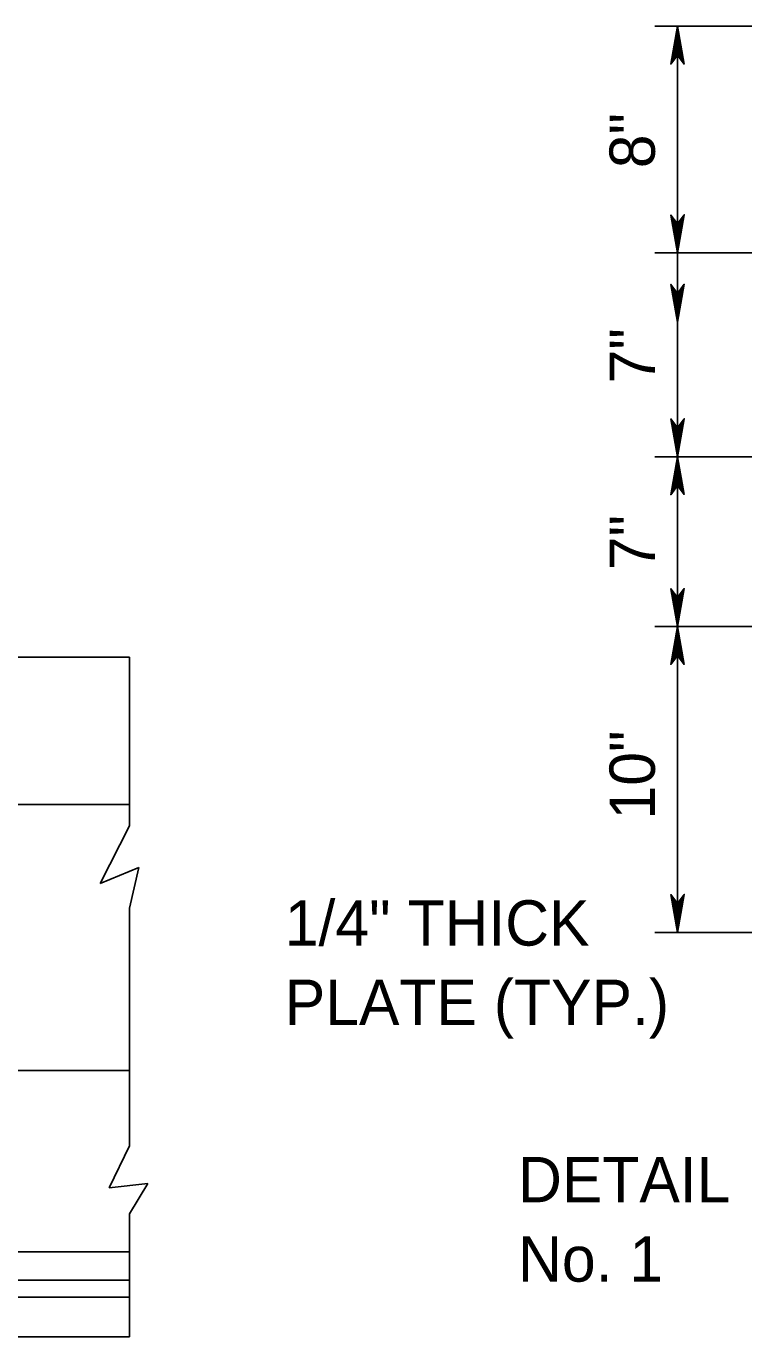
# Model space of a CAD drawing. Extents: x 499866 to 500993, y 499985 to 500645.
# Drawn here: x 500238.9 to 500302.2, y 500462.6 to 500578.2 of the extents above; entities that cross this region are included whole.
import ezdxf

# ---------------------------------------------------------------- set-up
doc = ezdxf.new("R2010")
doc.units = 0
doc.layers.add('24', color=7, linetype='Continuous')
doc.layers.add('5', color=7, linetype='Continuous')

msp = doc.modelspace()

# ---------------------------------------------------------------- linework, layer by layer
at = {"layer": '24'}
for points in [[(500296.34, 500578.18), (500295.74, 500574.83), (500296.34, 500575.63), (500296.92, 500574.84), (500296.34, 500578.18), (500296.34, 500577.95), (500295.79, 500574.92), (500296.34, 500575.69), (500296.87, 500574.98), (500296.35, 500577.83), (500296.34, 500577.72), (500295.87, 500575.12), (500296.34, 500575.71), (500296.8, 500575.11), (500296.34, 500577.67), (500296.35, 500577.56), (500295.94, 500575.29), (500296.34, 500575.73), (500296.74, 500575.28), (500296.35, 500577.24), (500296.35, 500577.05), (500296.03, 500575.46), (500296.33, 500575.77), (500296.66, 500575.43), (500296.34, 500577.01), (500296.33, 500576.83), (500296.12, 500575.64), (500296.35, 500575.87), (500296.58, 500575.62), (500296.34, 500576.67), (500296.32, 500576.5), (500296.18, 500575.78), (500296.34, 500575.9), (500296.52, 500575.71), (500296.34, 500576.41), (500296.22, 500575.95), (500296.35, 500576.01), (500296.48, 500575.81), (500296.35, 500576.3), (500296.28, 500575.99), (500296.38, 500576.12), (500296.44, 500575.97), (500296.34, 500576.12), (500296.33, 500576.04)], [(500296.34, 500558.19), (500296.93, 500561.54), (500296.34, 500560.74), (500295.75, 500561.52), (500296.34, 500558.19), (500296.33, 500558.41), (500296.88, 500561.45), (500296.33, 500560.68), (500295.8, 500561.39), (500296.32, 500558.53), (500296.34, 500558.65), (500296.8, 500561.24), (500296.33, 500560.66), (500295.87, 500561.26), (500296.34, 500558.7), (500296.32, 500558.81), (500296.73, 500561.08), (500296.34, 500560.64), (500295.93, 500561.09), (500296.32, 500559.13), (500296.32, 500559.32), (500296.65, 500560.91), (500296.35, 500560.6), (500296.01, 500560.93), (500296.34, 500559.35), (500296.35, 500559.53), (500296.55, 500560.73), (500296.32, 500560.5), (500296.09, 500560.75), (500296.34, 500559.7), (500296.35, 500559.87), (500296.49, 500560.58), (500296.33, 500560.47), (500296.15, 500560.66), (500296.34, 500559.95), (500296.45, 500560.42), (500296.32, 500560.35), (500296.19, 500560.56), (500296.32, 500560.07), (500296.4, 500560.38), (500296.3, 500560.25), (500296.23, 500560.4), (500296.33, 500560.25), (500296.35, 500560.33)], [(500296.34, 500552.06), (500296.93, 500555.41), (500296.34, 500554.61), (500295.75, 500555.4), (500296.34, 500552.06), (500296.33, 500552.29), (500296.88, 500555.32), (500296.33, 500554.55), (500295.8, 500555.26), (500296.32, 500552.41), (500296.34, 500552.52), (500296.8, 500555.12), (500296.33, 500554.53), (500295.87, 500555.13), (500296.34, 500552.57), (500296.32, 500552.68), (500296.73, 500554.95), (500296.34, 500554.51), (500295.93, 500554.96), (500296.32, 500553), (500296.32, 500553.19), (500296.65, 500554.78), (500296.35, 500554.47), (500296.01, 500554.81), (500296.34, 500553.23), (500296.35, 500553.4), (500296.55, 500554.6), (500296.32, 500554.37), (500296.09, 500554.62), (500296.34, 500553.57), (500296.35, 500553.74), (500296.49, 500554.46), (500296.33, 500554.34), (500296.15, 500554.53), (500296.34, 500553.83), (500296.45, 500554.29), (500296.32, 500554.23), (500296.19, 500554.43), (500296.32, 500553.94), (500296.4, 500554.25), (500296.3, 500554.12), (500296.23, 500554.27), (500296.33, 500554.12), (500296.35, 500554.2)], [(500296.34, 500540.2), (500296.93, 500543.55), (500296.34, 500542.75), (500295.75, 500543.54), (500296.34, 500540.2), (500296.33, 500540.43), (500296.88, 500543.46), (500296.33, 500542.69), (500295.8, 500543.4), (500296.32, 500540.55), (500296.34, 500540.66), (500296.8, 500543.26), (500296.33, 500542.67), (500295.87, 500543.27), (500296.34, 500540.71), (500296.32, 500540.82), (500296.73, 500543.09), (500296.34, 500542.65), (500295.93, 500543.1), (500296.32, 500541.14), (500296.32, 500541.33), (500296.65, 500542.92), (500296.35, 500542.61), (500296.01, 500542.95), (500296.34, 500541.37), (500296.35, 500541.55), (500296.55, 500542.74), (500296.32, 500542.51), (500296.09, 500542.76), (500296.34, 500541.71), (500296.35, 500541.88), (500296.49, 500542.6), (500296.33, 500542.48), (500296.15, 500542.67), (500296.34, 500541.97), (500296.45, 500542.44), (500296.32, 500542.37), (500296.19, 500542.57), (500296.32, 500542.08), (500296.4, 500542.39), (500296.3, 500542.26), (500296.23, 500542.41), (500296.33, 500542.26), (500296.35, 500542.34)], [(500296.34, 500540.2), (500295.74, 500536.85), (500296.34, 500537.66), (500296.92, 500536.87), (500296.34, 500540.2), (500296.34, 500539.98), (500295.79, 500536.95), (500296.34, 500537.72), (500296.87, 500537.01), (500296.35, 500539.86), (500296.34, 500539.75), (500295.87, 500537.15), (500296.34, 500537.73), (500296.8, 500537.14), (500296.34, 500539.7), (500296.35, 500539.59), (500295.94, 500537.32), (500296.34, 500537.76), (500296.74, 500537.31), (500296.35, 500539.26), (500296.35, 500539.08), (500296.03, 500537.49), (500296.33, 500537.79), (500296.66, 500537.46), (500296.34, 500539.04), (500296.33, 500538.86), (500296.12, 500537.67), (500296.35, 500537.9), (500296.58, 500537.65), (500296.34, 500538.7), (500296.32, 500538.53), (500296.18, 500537.81), (500296.34, 500537.93), (500296.52, 500537.73), (500296.34, 500538.44), (500296.22, 500537.97), (500296.35, 500538.04), (500296.48, 500537.84), (500296.35, 500538.32), (500296.28, 500538.02), (500296.38, 500538.15), (500296.44, 500538), (500296.34, 500538.15), (500296.33, 500538.07)], [(500296.34, 500525.22), (500296.93, 500528.57), (500296.34, 500527.77), (500295.75, 500528.55), (500296.34, 500525.22), (500296.33, 500525.44), (500296.88, 500528.47), (500296.33, 500527.7), (500295.8, 500528.41), (500296.32, 500525.56), (500296.34, 500525.67), (500296.8, 500528.27), (500296.33, 500527.69), (500295.87, 500528.29), (500296.34, 500525.72), (500296.32, 500525.83), (500296.73, 500528.1), (500296.34, 500527.66), (500295.93, 500528.11), (500296.32, 500526.16), (500296.32, 500526.35), (500296.65, 500527.94), (500296.35, 500527.63), (500296.01, 500527.96), (500296.34, 500526.38), (500296.35, 500526.56), (500296.55, 500527.75), (500296.32, 500527.52), (500296.09, 500527.77), (500296.34, 500526.72), (500296.35, 500526.89), (500296.49, 500527.61), (500296.33, 500527.49), (500296.15, 500527.69), (500296.34, 500526.98), (500296.45, 500527.45), (500296.32, 500527.38), (500296.19, 500527.58), (500296.32, 500527.1), (500296.4, 500527.4), (500296.3, 500527.27), (500296.23, 500527.42), (500296.33, 500527.28), (500296.35, 500527.35)], [(500296.34, 500525.22), (500295.74, 500521.87), (500296.34, 500522.67), (500296.92, 500521.88), (500296.34, 500525.22), (500296.34, 500524.99), (500295.79, 500521.96), (500296.34, 500522.73), (500296.87, 500522.02), (500296.35, 500524.87), (500296.34, 500524.76), (500295.87, 500522.16), (500296.34, 500522.75), (500296.8, 500522.15), (500296.34, 500524.71), (500296.35, 500524.6), (500295.94, 500522.33), (500296.34, 500522.77), (500296.74, 500522.32), (500296.35, 500524.28), (500296.35, 500524.09), (500296.03, 500522.5), (500296.33, 500522.81), (500296.66, 500522.47), (500296.34, 500524.05), (500296.33, 500523.87), (500296.12, 500522.68), (500296.35, 500522.91), (500296.58, 500522.66), (500296.34, 500523.71), (500296.32, 500523.54), (500296.18, 500522.82), (500296.34, 500522.94), (500296.52, 500522.75), (500296.34, 500523.45), (500296.22, 500522.99), (500296.35, 500523.05), (500296.48, 500522.85), (500296.35, 500523.34), (500296.28, 500523.03), (500296.38, 500523.16), (500296.44, 500523.01), (500296.34, 500523.16), (500296.33, 500523.08)], [(500296.34, 500498.24), (500296.93, 500501.59), (500296.34, 500500.79), (500295.75, 500501.57), (500296.34, 500498.24), (500296.33, 500498.46), (500296.88, 500501.49), (500296.33, 500500.72), (500295.8, 500501.43), (500296.32, 500498.58), (500296.34, 500498.69), (500296.8, 500501.29), (500296.33, 500500.71), (500295.87, 500501.31), (500296.34, 500498.74), (500296.32, 500498.85), (500296.73, 500501.12), (500296.34, 500500.68), (500295.93, 500501.13), (500296.32, 500499.18), (500296.32, 500499.37), (500296.65, 500500.96), (500296.35, 500500.65), (500296.01, 500500.98), (500296.34, 500499.4), (500296.35, 500499.58), (500296.55, 500500.77), (500296.32, 500500.54), (500296.09, 500500.79), (500296.34, 500499.74), (500296.35, 500499.91), (500296.49, 500500.63), (500296.33, 500500.51), (500296.15, 500500.71), (500296.34, 500500), (500296.45, 500500.47), (500296.32, 500500.4), (500296.19, 500500.61), (500296.32, 500500.12), (500296.4, 500500.42), (500296.3, 500500.3), (500296.23, 500500.44), (500296.33, 500500.3), (500296.35, 500500.37)]]:
    msp.add_lwpolyline(points, dxfattribs=at)
at = {"layer": '5'}
for p, q in [((500305.74, 500578.18), (500294.34, 500578.18)), ((500296.34, 500578.18), (500296.34, 500558.19)), ((500307.05, 500558.19), (500294.34, 500558.19)), ((500296.34, 500558.19), (500296.34, 500552.06)), ((500296.34, 500558.19), (500296.34, 500540.2)), ((500307.05, 500540.2), (500294.34, 500540.2)), ((500296.34, 500540.2), (500296.34, 500525.22)), ((500306, 500525.22), (500294.34, 500525.22)), ((500296.34, 500525.22), (500296.34, 500498.24)), ((500248.02, 500522.52), (500174.8, 500522.52)), ((500248.02, 500522.52), (500248.02, 500507.65)), ((500248.02, 500509.53), (500176.8, 500509.53)), ((500248.02, 500507.65), (500245.43, 500502.55)), ((500248.83, 500503.95), (500245.43, 500502.55)), ((500248.02, 500500.36), (500248.83, 500503.95)), ((500248.02, 500500.36), (500248.02, 500479.4)), ((500305.74, 500498.24), (500294.34, 500498.24)), ((500248.02, 500486.05), (500166.8, 500486.05)), ((500248.02, 500479.4), (500246.23, 500475.7)), ((500249.63, 500476.1), (500246.23, 500475.7)), ((500248.02, 500473.41), (500249.63, 500476.1)), ((500248.02, 500473.41), (500248.02, 500462.56)), ((500248.02, 500470.06), (500176.8, 500470.06)), ((500248.02, 500467.56), (500166.8, 500467.56)), ((500248.02, 500466.06), (500166.8, 500466.06)), ((500248.02, 500462.56), (500166.8, 500462.56))]:
    msp.add_line(p, q, dxfattribs=at)

# ---------------------------------------------------------------- texts
for s, p in [('8"', (500294.34, 500565.65)), ('7"', (500294.34, 500546.67)), ('7"', (500294.34, 500530.19)), ('10"', (500294.34, 500508.2))]:
    msp.add_text(s, height=4, rotation=90, dxfattribs=at).set_placement(p)
for s, p in [('1/4" THICK', (500261.71, 500497.07)), ('PLATE (TYP.)', (500261.71, 500490.07)), ('DETAIL', (500282.28, 500474.43)), ('No. 1', (500282.28, 500467.43))]:
    msp.add_text(s, height=4, dxfattribs=at).set_placement(p)

doc.saveas('drawing.dxf')
